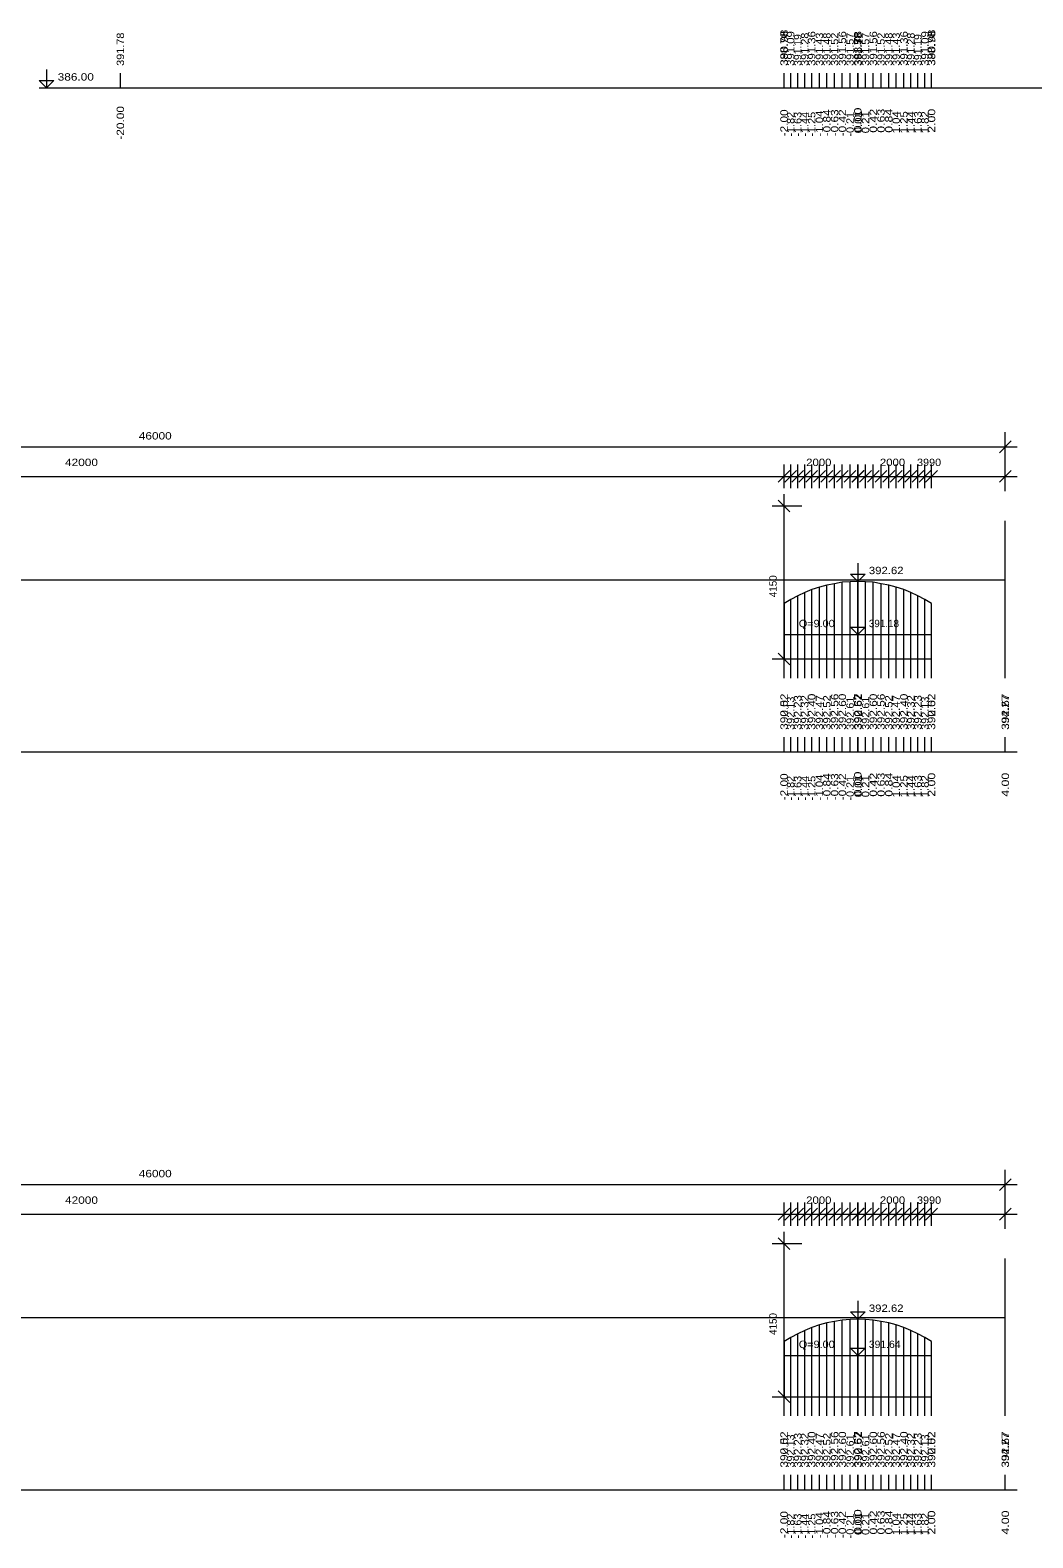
# Model space of a CAD drawing. Extents: x 7 to 442, y -393 to 441.
# Drawn here: x 279.19 to 306.38, y 354.89 to 395.77 of the extents above; entities that cross this region are included whole.
import ezdxf

# ---------------------------------------------------------------- set-up
doc = ezdxf.new("R2010")
doc.units = 0
doc.header["$LTSCALE"] = 0.08
doc.layers.add('7', color=7, linetype='Continuous', lineweight=13)

msp = doc.modelspace()

# ---------------------------------------------------------------- linework, layer by layer
at = {"layer": '7'}
for p, q in [((281.635, 394.2), (281.635, 394.6)), ((299.635, 394.2), (299.635, 394.6)), ((299.635, 394.2), (299.635, 394.6)), ((299.815, 394.2), (299.815, 394.6)), ((300.005, 394.2), (300.005, 394.6)), ((300.195, 394.2), (300.195, 394.6)), ((300.385, 394.2), (300.385, 394.6)), ((300.595, 394.2), (300.595, 394.6)), ((300.795, 394.2), (300.795, 394.6)), ((301.005, 394.2), (301.005, 394.6)), ((301.215, 394.2), (301.215, 394.6)), ((301.425, 394.2), (301.425, 394.6)), ((301.635, 394.2), (301.635, 394.6)), ((301.635, 394.2), (301.635, 394.6)), ((301.635, 394.2), (301.635, 394.6)), ((301.645, 394.2), (301.645, 394.6)), ((301.645, 394.2), (301.645, 394.6)), ((301.845, 394.2), (301.845, 394.6)), ((302.055, 394.2), (302.055, 394.6)), ((302.265, 394.2), (302.265, 394.6)), ((302.475, 394.2), (302.475, 394.6)), ((302.675, 394.2), (302.675, 394.6)), ((302.885, 394.2), (302.885, 394.6)), ((303.075, 394.2), (303.075, 394.6)), ((303.265, 394.2), (303.265, 394.6)), ((303.455, 394.2), (303.455, 394.6)), ((303.635, 394.2), (303.635, 394.6)), ((303.635, 394.2), (303.635, 394.6)), ((279.435, 394.2), (321.955, 394.2)), ((305.475, 384.31), (305.795, 384.63)), ((305.635, 383.27), (305.635, 384.87)), ((259.315, 384.47), (305.955, 384.47)), ((299.475, 383.51), (299.795, 383.83)), ((299.475, 383.51), (299.795, 383.83)), ((299.635, 383.35), (299.635, 383.99)), ((299.635, 383.35), (299.635, 383.99)), ((299.655, 383.51), (299.975, 383.83)), ((299.815, 383.35), (299.815, 383.99)), ((299.845, 383.51), (300.165, 383.83)), ((300.005, 383.35), (300.005, 383.99)), ((300.035, 383.51), (300.355, 383.83)), ((300.195, 383.35), (300.195, 383.99)), ((300.225, 383.51), (300.545, 383.83)), ((300.385, 383.35), (300.385, 383.99)), ((300.435, 383.51), (300.755, 383.83)), ((300.595, 383.35), (300.595, 383.99)), ((300.635, 383.51), (300.955, 383.83)), ((300.795, 383.35), (300.795, 383.99)), ((300.845, 383.51), (301.165, 383.83)), ((301.005, 383.35), (301.005, 383.99)), ((301.055, 383.51), (301.375, 383.83)), ((301.215, 383.35), (301.215, 383.99)), ((301.265, 383.51), (301.585, 383.83)), ((301.425, 383.35), (301.425, 383.99)), ((301.475, 383.51), (301.795, 383.83)), ((301.475, 383.51), (301.795, 383.83)), ((301.475, 383.51), (301.795, 383.83)), ((301.485, 383.51), (301.805, 383.83)), ((301.485, 383.51), (301.805, 383.83)), ((301.635, 383.35), (301.635, 383.99)), ((301.635, 383.35), (301.635, 383.99)), ((301.635, 383.35), (301.635, 383.99)), ((301.645, 383.35), (301.645, 383.99)), ((301.645, 383.35), (301.645, 383.99)), ((301.685, 383.51), (302.005, 383.83)), ((301.845, 383.35), (301.845, 383.99)), ((301.895, 383.51), (302.215, 383.83)), ((302.055, 383.35), (302.055, 383.99)), ((302.105, 383.51), (302.425, 383.83)), ((302.265, 383.35), (302.265, 383.99)), ((302.315, 383.51), (302.635, 383.83)), ((302.475, 383.35), (302.475, 383.99)), ((302.515, 383.51), (302.835, 383.83)), ((302.675, 383.35), (302.675, 383.99)), ((302.725, 383.51), (303.045, 383.83)), ((302.885, 383.35), (302.885, 383.99)), ((302.915, 383.51), (303.235, 383.83)), ((303.075, 383.35), (303.075, 383.99)), ((303.105, 383.51), (303.425, 383.83)), ((303.265, 383.35), (303.265, 383.99)), ((303.295, 383.51), (303.615, 383.83)), ((303.455, 383.35), (303.455, 383.99)), ((303.475, 383.51), (303.795, 383.83)), ((303.475, 383.51), (303.795, 383.83)), ((303.635, 383.35), (303.635, 383.99)), ((303.635, 383.35), (303.635, 383.99)), ((305.475, 383.51), (305.795, 383.83)), ((305.475, 383.51), (305.795, 383.83)), ((305.635, 383.35), (305.635, 383.99)), ((305.635, 383.35), (305.635, 383.99)), ((259.315, 383.67), (305.955, 383.67)), ((299.795, 382.71), (299.475, 383.03)), ((299.635, 378.56), (299.635, 383.19)), ((299.315, 382.87), (300.115, 382.87)), ((305.635, 378.2), (305.635, 382.47)), ((300.385, 378.2), (300.385, 380.6)), ((300.595, 378.2), (300.595, 380.67)), ((300.795, 378.2), (300.795, 380.72)), ((301.005, 378.2), (301.005, 380.76)), ((301.215, 378.2), (301.215, 380.8)), ((301.425, 378.2), (301.425, 380.81)), ((301.635, 378.2), (301.635, 380.87)), ((301.635, 378.2), (301.635, 380.82)), ((301.635, 380.82), (301.645, 380.82)), ((301.645, 378.2), (301.645, 380.87)), ((301.645, 378.2), (301.645, 380.82)), ((301.845, 378.2), (301.845, 380.81)), ((302.055, 378.2), (302.055, 380.8)), ((302.265, 378.2), (302.265, 380.76)), ((302.475, 378.2), (302.475, 380.72)), ((302.675, 378.2), (302.675, 380.67)), ((302.885, 378.2), (302.885, 380.6)), ((305.635, 378.2), (305.635, 380.87)), ((299.635, 378.2), (299.635, 380.22)), ((299.815, 378.2), (299.815, 380.33)), ((300.005, 378.2), (300.005, 380.43)), ((300.195, 378.2), (300.195, 380.52)), ((303.075, 378.2), (303.075, 380.52)), ((303.265, 378.2), (303.265, 380.43)), ((303.455, 378.2), (303.455, 380.33)), ((303.635, 378.2), (303.635, 380.22)), ((299.635, 379.383), (303.635, 379.383)), ((299.315, 378.72), (300.115, 378.72)), ((299.795, 378.56), (299.475, 378.88)), ((299.635, 378.2), (299.635, 378.72)), ((301.635, 378.2), (301.635, 378.72)), ((303.635, 378.2), (303.635, 378.72)), ((299.635, 376.2), (299.635, 376.6)), ((299.635, 376.2), (299.635, 376.6)), ((299.815, 376.2), (299.815, 376.6)), ((300.005, 376.2), (300.005, 376.6)), ((300.195, 376.2), (300.195, 376.6)), ((300.385, 376.2), (300.385, 376.6)), ((300.595, 376.2), (300.595, 376.6)), ((300.795, 376.2), (300.795, 376.6)), ((301.005, 376.2), (301.005, 376.6)), ((301.215, 376.2), (301.215, 376.6)), ((301.425, 376.2), (301.425, 376.6)), ((301.635, 376.2), (301.635, 376.6)), ((301.635, 376.2), (301.635, 376.6)), ((301.635, 376.2), (301.635, 376.6)), ((301.645, 376.2), (301.645, 376.6)), ((301.645, 376.2), (301.645, 376.6)), ((301.845, 376.2), (301.845, 376.6)), ((302.055, 376.2), (302.055, 376.6)), ((302.265, 376.2), (302.265, 376.6)), ((302.475, 376.2), (302.475, 376.6)), ((302.675, 376.2), (302.675, 376.6)), ((302.885, 376.2), (302.885, 376.6)), ((303.075, 376.2), (303.075, 376.6)), ((303.265, 376.2), (303.265, 376.6)), ((303.455, 376.2), (303.455, 376.6)), ((303.635, 376.2), (303.635, 376.6)), ((303.635, 376.2), (303.635, 376.6)), ((305.635, 376.2), (305.635, 376.6)), ((305.635, 376.2), (305.635, 376.6)), ((257.435, 376.2), (305.955, 376.2)), ((305.475, 364.31), (305.795, 364.63)), ((305.635, 363.27), (305.635, 364.87)), ((259.315, 364.47), (305.955, 364.47)), ((299.475, 363.51), (299.795, 363.83)), ((299.475, 363.51), (299.795, 363.83)), ((299.635, 363.35), (299.635, 363.99)), ((299.635, 363.35), (299.635, 363.99)), ((299.655, 363.51), (299.975, 363.83)), ((299.815, 363.35), (299.815, 363.99)), ((299.845, 363.51), (300.165, 363.83)), ((300.005, 363.35), (300.005, 363.99)), ((300.035, 363.51), (300.355, 363.83)), ((300.195, 363.35), (300.195, 363.99)), ((300.225, 363.51), (300.545, 363.83)), ((300.385, 363.35), (300.385, 363.99)), ((300.435, 363.51), (300.755, 363.83)), ((300.595, 363.35), (300.595, 363.99)), ((300.635, 363.51), (300.955, 363.83)), ((300.795, 363.35), (300.795, 363.99)), ((300.845, 363.51), (301.165, 363.83)), ((301.005, 363.35), (301.005, 363.99)), ((301.055, 363.51), (301.375, 363.83)), ((301.215, 363.35), (301.215, 363.99)), ((301.265, 363.51), (301.585, 363.83)), ((301.425, 363.35), (301.425, 363.99)), ((301.475, 363.51), (301.795, 363.83)), ((301.475, 363.51), (301.795, 363.83)), ((301.475, 363.51), (301.795, 363.83)), ((301.485, 363.51), (301.805, 363.83)), ((301.485, 363.51), (301.805, 363.83)), ((301.635, 363.35), (301.635, 363.99)), ((301.635, 363.35), (301.635, 363.99)), ((301.635, 363.35), (301.635, 363.99)), ((301.645, 363.35), (301.645, 363.99)), ((301.645, 363.35), (301.645, 363.99)), ((301.685, 363.51), (302.005, 363.83)), ((301.845, 363.35), (301.845, 363.99)), ((301.895, 363.51), (302.215, 363.83)), ((302.055, 363.35), (302.055, 363.99)), ((302.105, 363.51), (302.425, 363.83)), ((302.265, 363.35), (302.265, 363.99)), ((302.315, 363.51), (302.635, 363.83)), ((302.475, 363.35), (302.475, 363.99)), ((302.515, 363.51), (302.835, 363.83)), ((302.675, 363.35), (302.675, 363.99)), ((302.725, 363.51), (303.045, 363.83)), ((302.885, 363.35), (302.885, 363.99)), ((302.915, 363.51), (303.235, 363.83)), ((303.075, 363.35), (303.075, 363.99)), ((303.105, 363.51), (303.425, 363.83)), ((303.265, 363.35), (303.265, 363.99)), ((303.295, 363.51), (303.615, 363.83)), ((303.455, 363.35), (303.455, 363.99)), ((303.475, 363.51), (303.795, 363.83)), ((303.475, 363.51), (303.795, 363.83)), ((303.635, 363.35), (303.635, 363.99)), ((303.635, 363.35), (303.635, 363.99)), ((305.475, 363.51), (305.795, 363.83)), ((305.475, 363.51), (305.795, 363.83)), ((305.635, 363.35), (305.635, 363.99)), ((305.635, 363.35), (305.635, 363.99)), ((259.315, 363.67), (305.955, 363.67)), ((299.795, 362.71), (299.475, 363.03)), ((299.635, 358.56), (299.635, 363.19)), ((299.315, 362.87), (300.115, 362.87)), ((305.635, 358.2), (305.635, 362.47)), ((300.195, 358.2), (300.195, 360.52)), ((300.385, 358.2), (300.385, 360.6)), ((300.595, 358.2), (300.595, 360.67)), ((300.795, 358.2), (300.795, 360.72)), ((301.005, 358.2), (301.005, 360.76)), ((301.215, 358.2), (301.215, 360.8)), ((301.425, 358.2), (301.425, 360.81)), ((301.635, 358.2), (301.635, 360.87)), ((301.635, 358.2), (301.635, 360.82)), ((301.635, 360.82), (301.645, 360.82)), ((301.645, 358.2), (301.645, 360.87)), ((301.645, 358.2), (301.645, 360.82)), ((301.845, 358.2), (301.845, 360.81)), ((302.055, 358.2), (302.055, 360.8)), ((302.265, 358.2), (302.265, 360.76)), ((302.475, 358.2), (302.475, 360.72)), ((302.675, 358.2), (302.675, 360.67)), ((302.885, 358.2), (302.885, 360.6)), ((303.075, 358.2), (303.075, 360.52)), ((305.635, 358.2), (305.635, 360.87)), ((299.635, 358.2), (299.635, 360.22)), ((299.815, 358.2), (299.815, 360.33)), ((300.005, 358.2), (300.005, 360.43)), ((303.265, 358.2), (303.265, 360.43)), ((303.455, 358.2), (303.455, 360.33)), ((303.635, 358.2), (303.635, 360.22)), ((299.635, 359.841), (303.635, 359.841)), ((299.795, 358.56), (299.475, 358.88)), ((299.315, 358.72), (300.115, 358.72)), ((299.635, 358.2), (299.635, 358.72)), ((301.635, 358.2), (301.635, 358.72)), ((303.635, 358.2), (303.635, 358.72)), ((299.635, 356.2), (299.635, 356.6)), ((299.635, 356.2), (299.635, 356.6)), ((299.815, 356.2), (299.815, 356.6)), ((300.005, 356.2), (300.005, 356.6)), ((300.195, 356.2), (300.195, 356.6)), ((300.385, 356.2), (300.385, 356.6)), ((300.595, 356.2), (300.595, 356.6)), ((300.795, 356.2), (300.795, 356.6)), ((301.005, 356.2), (301.005, 356.6)), ((301.215, 356.2), (301.215, 356.6)), ((301.425, 356.2), (301.425, 356.6)), ((301.635, 356.2), (301.635, 356.6)), ((301.635, 356.2), (301.635, 356.6)), ((301.635, 356.2), (301.635, 356.6)), ((301.645, 356.2), (301.645, 356.6)), ((301.645, 356.2), (301.645, 356.6)), ((301.845, 356.2), (301.845, 356.6)), ((302.055, 356.2), (302.055, 356.6)), ((302.265, 356.2), (302.265, 356.6)), ((302.475, 356.2), (302.475, 356.6)), ((302.675, 356.2), (302.675, 356.6)), ((302.885, 356.2), (302.885, 356.6)), ((303.075, 356.2), (303.075, 356.6)), ((303.265, 356.2), (303.265, 356.6)), ((303.455, 356.2), (303.455, 356.6)), ((303.635, 356.2), (303.635, 356.6)), ((303.635, 356.2), (303.635, 356.6)), ((305.635, 356.2), (305.635, 356.6)), ((305.635, 356.2), (305.635, 356.6)), ((257.435, 356.2), (305.955, 356.2))]:
    msp.add_line(p, q, dxfattribs=at)
for points in [[(279.635, 394.7), (279.635, 394.2), (279.435, 394.4), (279.835, 394.4), (279.635, 394.2)], [(259.635, 380.87), (301.635, 380.87), (301.635, 380.82), (301.425, 380.81), (301.215, 380.8), (301.005, 380.76), (300.795, 380.72), (300.595, 380.67), (300.385, 380.6), (300.195, 380.52), (300.005, 380.43), (299.815, 380.33), (299.635, 380.22), (299.635, 378.72), (301.635, 378.72), (303.635, 378.72), (303.635, 380.22), (303.455, 380.33), (303.265, 380.43), (303.075, 380.52), (302.885, 380.6), (302.675, 380.67), (302.475, 380.72), (302.265, 380.76), (302.055, 380.8), (301.845, 380.81), (301.645, 380.82), (301.645, 380.87), (305.635, 380.87), (305.635, 382.47)], [(301.635, 381.32), (301.635, 380.82), (301.435, 381.02), (301.835, 381.02), (301.635, 380.82)], [(301.635, 379.883), (301.635, 379.383), (301.435, 379.583), (301.835, 379.583), (301.635, 379.383)], [(259.635, 360.87), (301.635, 360.87), (301.635, 360.82), (301.425, 360.81), (301.215, 360.8), (301.005, 360.76), (300.795, 360.72), (300.595, 360.67), (300.385, 360.6), (300.195, 360.52), (300.005, 360.43), (299.815, 360.33), (299.635, 360.22), (299.635, 358.72), (301.635, 358.72), (303.635, 358.72), (303.635, 360.22), (303.455, 360.33), (303.265, 360.43), (303.075, 360.52), (302.885, 360.6), (302.675, 360.67), (302.475, 360.72), (302.265, 360.76), (302.055, 360.8), (301.845, 360.81), (301.645, 360.82), (301.645, 360.87), (305.635, 360.87), (305.635, 362.47)], [(301.635, 361.32), (301.635, 360.82), (301.435, 361.02), (301.835, 361.02), (301.635, 360.82)], [(301.635, 360.341), (301.635, 359.841), (301.435, 360.041), (301.835, 360.041), (301.635, 359.841)]]:
    msp.add_lwpolyline(points, dxfattribs=at)

# ---------------------------------------------------------------- texts
for s, width, p in [('391.78 ', 1.1, (281.735, 394.8)), ('390.98 ', 1.2, (299.735, 394.8)), ('388.78 ', 1.15, (299.735, 394.8)), ('391.09 ', 1.15, (299.915, 394.8)), ('391.28 ', 1.1, (300.295, 394.8)), ('391.36 ', 1.15, (300.485, 394.8)), ('391.43 ', 1.1, (300.695, 394.8)), ('391.48 ', 1.1, (300.895, 394.8)), ('391.52 ', 1.1, (301.105, 394.8)), ('391.56 ', 1.15, (301.315, 394.8)), ('391.57 ', 1.1, (301.525, 394.8)), ('388.78 ', 1.15, (301.735, 394.8)), ('391.78 ', 1.1, (301.735, 394.8)), ('391.58 ', 1.1, (301.735, 394.8)), ('391.58 ', 1.1, (301.745, 394.8)), ('391.78 ', 1.1, (301.745, 394.8)), ('391.57 ', 1.1, (301.945, 394.8)), ('391.56 ', 1.15, (302.155, 394.8)), ('391.52 ', 1.1, (302.365, 394.8)), ('391.48 ', 1.1, (302.575, 394.8)), ('391.43 ', 1.1, (302.775, 394.8)), ('391.36 ', 1.15, (302.985, 394.8)), ('391.28 ', 1.1, (303.175, 394.8)), ('391.09 ', 1.15, (303.555, 394.8)), ('390.98 ', 1.2, (303.735, 394.8)), ('388.78 ', 1.15, (303.735, 394.8)), ('391.19 ', 1.05, (300.105, 394.8)), ('391.19 ', 1.05, (303.365, 394.8)), ('-20.00 ', 1.2, (281.735, 392.8)), (' -2.00 ', 1.2, (299.735, 392.8)), (' -2.00 ', 1.2, (299.735, 392.8)), (' -0.84 ', 1.2, (300.895, 392.8)), (' -0.63 ', 1.2, (301.105, 392.8)), ('  0.00 ', 1.3, (301.735, 392.8)), ('  0.00 ', 1.3, (301.735, 392.8)), ('  0.00 ', 1.3, (301.735, 392.8)), ('  0.42 ', 1.25, (302.155, 392.8)), ('  0.63 ', 1.25, (302.365, 392.8)), ('  0.84 ', 1.25, (302.575, 392.8)), ('  2.00 ', 1.25, (303.735, 392.8)), ('  2.00 ', 1.25, (303.735, 392.8)), (' -1.82 ', 1.1, (299.915, 392.8)), (' -1.63 ', 1.1, (300.105, 392.8)), (' -1.44 ', 1.1, (300.295, 392.8)), (' -1.25 ', 1.1, (300.485, 392.8)), (' -1.04 ', 1.15, (300.695, 392.8)), (' -0.42 ', 1.2, (301.315, 392.8)), (' -0.21 ', 1.1, (301.525, 392.8)), ('  0.01 ', 1.15, (301.745, 392.8)), ('  0.01 ', 1.15, (301.745, 392.8)), ('  0.21 ', 1.15, (301.945, 392.8)), ('  1.04 ', 1.15, (302.775, 392.8)), ('  1.25 ', 1.15, (302.985, 392.8)), ('  1.44 ', 1.15, (303.175, 392.8)), ('  1.63 ', 1.15, (303.365, 392.8)), ('  1.82 ', 1.15, (303.555, 392.8)), ('392.02 ', 1.2, (299.735, 376.8)), ('390.52 ', 1.2, (299.735, 376.8)), ('392.13 ', 1.1, (299.915, 376.8)), ('392.23 ', 1.15, (300.105, 376.8)), ('392.32 ', 1.15, (300.295, 376.8)), ('392.40 ', 1.2, (300.485, 376.8)), ('392.47 ', 1.15, (300.695, 376.8)), ('392.52 ', 1.15, (300.895, 376.8)), ('392.56 ', 1.2, (301.105, 376.8)), ('392.60 ', 1.2, (301.315, 376.8)), ('392.61 ', 1.1, (301.525, 376.8)), ('392.67 ', 1.2, (301.735, 376.8)), ('392.62 ', 1.2, (301.735, 376.8)), ('390.52 ', 1.2, (301.735, 376.8)), ('392.62 ', 1.2, (301.745, 376.8)), ('392.67 ', 1.2, (301.745, 376.8)), ('392.61 ', 1.1, (301.945, 376.8)), ('392.60 ', 1.2, (302.155, 376.8)), ('392.56 ', 1.2, (302.365, 376.8)), ('392.52 ', 1.15, (302.575, 376.8)), ('392.47 ', 1.15, (302.775, 376.8)), ('392.40 ', 1.2, (302.985, 376.8)), ('392.32 ', 1.15, (303.175, 376.8)), ('392.23 ', 1.15, (303.365, 376.8)), ('392.13 ', 1.1, (303.555, 376.8)), ('390.52 ', 1.2, (303.735, 376.8)), ('392.02 ', 1.2, (303.735, 376.8)), ('392.67 ', 1.2, (305.735, 376.8)), ('394.27 ', 1.15, (305.735, 376.8)), ('  0.00 ', 1.3, (301.735, 374.8)), ('  0.00 ', 1.3, (301.735, 374.8)), ('  0.00 ', 1.3, (301.735, 374.8)), ('  0.63 ', 1.25, (302.365, 374.8)), ('  0.84 ', 1.25, (302.575, 374.8)), ('  2.00 ', 1.25, (303.735, 374.8)), ('  2.00 ', 1.25, (303.735, 374.8)), ('  4.00 ', 1.25, (305.735, 374.8)), ('  4.00 ', 1.25, (305.735, 374.8)), (' -2.00 ', 1.2, (299.735, 374.8)), (' -2.00 ', 1.2, (299.735, 374.8)), (' -1.82 ', 1.1, (299.915, 374.8)), (' -1.63 ', 1.1, (300.105, 374.8)), (' -1.44 ', 1.1, (300.295, 374.8)), (' -1.25 ', 1.1, (300.485, 374.8)), (' -1.04 ', 1.15, (300.695, 374.8)), (' -0.84 ', 1.2, (300.895, 374.8)), (' -0.63 ', 1.2, (301.105, 374.8)), (' -0.42 ', 1.2, (301.315, 374.8)), (' -0.21 ', 1.1, (301.525, 374.8)), ('  0.01 ', 1.15, (301.745, 374.8)), ('  0.01 ', 1.15, (301.745, 374.8)), ('  0.21 ', 1.15, (301.945, 374.8)), ('  0.42 ', 1.25, (302.155, 374.8)), ('  1.04 ', 1.15, (302.775, 374.8)), ('  1.25 ', 1.15, (302.985, 374.8)), ('  1.44 ', 1.15, (303.175, 374.8)), ('  1.63 ', 1.15, (303.365, 374.8)), ('  1.82 ', 1.15, (303.555, 374.8)), ('392.02 ', 1.2, (299.735, 356.8)), ('390.52 ', 1.2, (299.735, 356.8)), ('392.13 ', 1.1, (299.915, 356.8)), ('392.23 ', 1.15, (300.105, 356.8)), ('392.32 ', 1.15, (300.295, 356.8)), ('392.40 ', 1.2, (300.485, 356.8)), ('392.47 ', 1.15, (300.695, 356.8)), ('392.52 ', 1.15, (300.895, 356.8)), ('392.56 ', 1.2, (301.105, 356.8)), ('392.60 ', 1.2, (301.315, 356.8)), ('392.61 ', 1.1, (301.525, 356.8)), ('392.67 ', 1.2, (301.735, 356.8)), ('392.62 ', 1.2, (301.735, 356.8)), ('390.52 ', 1.2, (301.735, 356.8)), ('392.62 ', 1.2, (301.745, 356.8)), ('392.67 ', 1.2, (301.745, 356.8)), ('392.61 ', 1.1, (301.945, 356.8)), ('392.60 ', 1.2, (302.155, 356.8)), ('392.56 ', 1.2, (302.365, 356.8)), ('392.52 ', 1.15, (302.575, 356.8)), ('392.47 ', 1.15, (302.775, 356.8)), ('392.40 ', 1.2, (302.985, 356.8)), ('392.32 ', 1.15, (303.175, 356.8)), ('392.23 ', 1.15, (303.365, 356.8)), ('392.13 ', 1.1, (303.555, 356.8)), ('390.52 ', 1.2, (303.735, 356.8)), ('392.02 ', 1.2, (303.735, 356.8)), ('392.67 ', 1.2, (305.735, 356.8)), ('394.27 ', 1.15, (305.735, 356.8)), (' -2.00 ', 1.2, (299.735, 354.8)), (' -2.00 ', 1.2, (299.735, 354.8)), (' -0.84 ', 1.2, (300.895, 354.8)), (' -0.63 ', 1.2, (301.105, 354.8)), (' -0.42 ', 1.2, (301.315, 354.8)), ('  0.00 ', 1.3, (301.735, 354.8)), ('  0.00 ', 1.3, (301.735, 354.8)), ('  0.00 ', 1.3, (301.735, 354.8)), ('  0.42 ', 1.25, (302.155, 354.8)), ('  0.63 ', 1.25, (302.365, 354.8)), ('  0.84 ', 1.25, (302.575, 354.8)), ('  2.00 ', 1.25, (303.735, 354.8)), ('  2.00 ', 1.25, (303.735, 354.8)), ('  4.00 ', 1.25, (305.735, 354.8)), ('  4.00 ', 1.25, (305.735, 354.8)), (' -1.82 ', 1.1, (299.915, 354.8)), (' -1.63 ', 1.1, (300.105, 354.8)), (' -1.44 ', 1.1, (300.295, 354.8)), (' -1.25 ', 1.1, (300.485, 354.8)), (' -1.04 ', 1.15, (300.695, 354.8)), (' -0.21 ', 1.1, (301.525, 354.8)), ('  0.01 ', 1.15, (301.745, 354.8)), ('  0.01 ', 1.15, (301.745, 354.8)), ('  0.21 ', 1.15, (301.945, 354.8)), ('  1.04 ', 1.15, (302.775, 354.8)), ('  1.25 ', 1.15, (302.985, 354.8)), ('  1.44 ', 1.15, (303.175, 354.8)), ('  1.63 ', 1.15, (303.365, 354.8)), ('  1.82 ', 1.15, (303.555, 354.8))]:
    msp.add_text(s, height=0.2, rotation=90, dxfattribs=dict(at, width=width)).set_placement(p)
for s, width, p in [('386.00', 1.2, (279.935, 394.4)), ('46000', 1.2, (282.135, 384.67)), ('42000', 1.2, (280.135, 383.95)), ('2000', 1.15, (300.235, 383.95)), ('2000', 1.15, (302.235, 383.95)), ('3990', 1.1, (303.24, 383.95)), ('392.62', 1.15, (301.935, 381.02)), ('Q=9.00', 1.1, (300.035, 379.583)), ('46000', 1.2, (282.135, 364.67)), ('42000', 1.2, (280.135, 363.95)), ('2000', 1.15, (300.235, 363.95)), ('2000', 1.15, (302.235, 363.95)), ('3990', 1.1, (303.24, 363.95)), ('392.62', 1.15, (301.935, 361.02)), ('Q=9.00', 1.1, (300.035, 360.041)), ('391.64', 1.05, (301.935, 360.041))]:
    msp.add_text(s, height=0.2, dxfattribs=dict(at, width=width)).set_placement(p)
for p in [(299.435, 380.395), (299.435, 360.395)]:
    msp.add_text('4150', height=0.2, rotation=90, dxfattribs=at).set_placement(p)
msp.add_text('391.18', height=0.2, dxfattribs=at).set_placement((301.935, 379.583))

doc.saveas('drawing.dxf')
